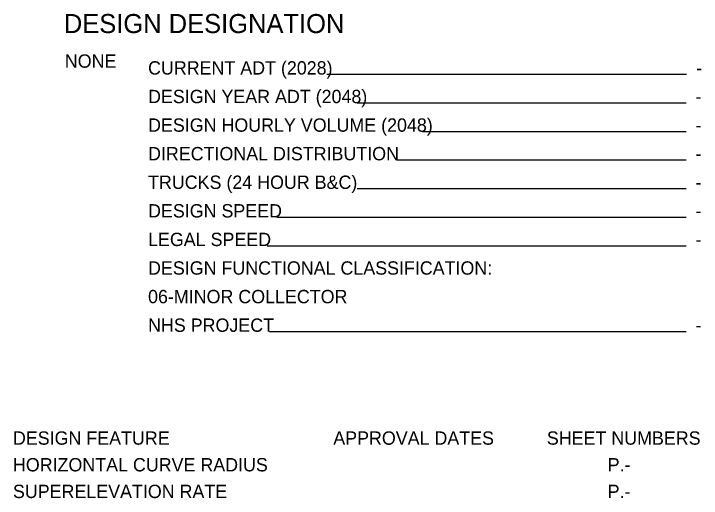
# Model space of a CAD drawing. Extents: x -8.3 to 34, y 0 to 22.
# Drawn here: x -8.32 to -1.11, y 4.98 to 10.07 of the extents above; entities that cross this region are included whole.
import ezdxf

# ---------------------------------------------------------------- set-up
doc = ezdxf.new("R2010")
doc.units = 0
doc.layers.add('SH_Data', color=7, linetype='Continuous')
doc.layers.add('SH_Text', color=7, linetype='Continuous')

msp = doc.modelspace()

# ---------------------------------------------------------------- linework, layer by layer
at = {"layer": 'SH_Data'}
for p, q in [((-1.2678, 9.4311), (-5.0392, 9.4311)), ((-1.2734, 9.1311), (-4.7217, 9.1311)), ((-1.2734, 8.8311), (-4.0379, 8.8311)), ((-1.2734, 8.5311), (-4.3065, 8.5311)), ((-1.2734, 8.2311), (-4.7217, 8.2311)), ((-1.2734, 7.9311), (-5.5643, 7.9311)), ((-1.2734, 7.6311), (-5.6681, 7.6311)), ((-1.2734, 6.7311), (-5.6433, 6.7311))]:
    msp.add_line(p, q, dxfattribs=at)

# ---------------------------------------------------------------- texts
msp.add_text('DESIGN DESIGNATION', height=0.2, dxfattribs=at).set_placement((-7.7991, 9.8666))
at = {"layer": 'SH_Text'}
for s, p in [('NONE', (-7.7889, 9.503)), ('CURRENT ADT (2028)', (-6.9158, 9.4311)), ('-', (-1.1678, 9.4311)), ('DESIGN YEAR ADT (2048)', (-6.9158, 9.1311)), ('-', (-1.1734, 9.1311)), ('DESIGN HOURLY VOLUME (2048)', (-6.9158, 8.8311)), ('-', (-1.1734, 8.8311)), ('DIRECTIONAL DISTRIBUTION', (-6.9158, 8.5311)), ('-', (-1.1734, 8.5311)), ('TRUCKS (24 HOUR B&C)', (-6.9158, 8.2311)), ('-', (-1.1734, 8.2311)), ('DESIGN SPEED', (-6.9158, 7.9311)), ('-', (-1.1734, 7.9311)), ('LEGAL SPEED', (-6.9158, 7.6311)), ('-', (-1.1734, 7.6311)), ('DESIGN FUNCTIONAL CLASSIFICATION:', (-6.9158, 7.3311)), ('06-MINOR COLLECTOR', (-6.9158, 7.0311)), ('NHS PROJECT', (-6.9158, 6.7311)), ('-', (-1.1734, 6.7311)), ('DESIGN FEATURE', (-8.3331, 5.5463)), ('APPROVAL DATES', (-4.9731, 5.5463)), ('SHEET NUMBERS', (-2.7331, 5.5463)), ('HORIZONTAL CURVE RADIUS', (-8.3331, 5.2663)), ('P.-', (-2.0953, 5.2663)), ('SUPERELEVATION RATE', (-8.3331, 4.9863)), ('P.-', (-2.0953, 4.9863))]:
    msp.add_text(s, height=0.14, dxfattribs=at).set_placement(p)

doc.saveas('drawing.dxf')
